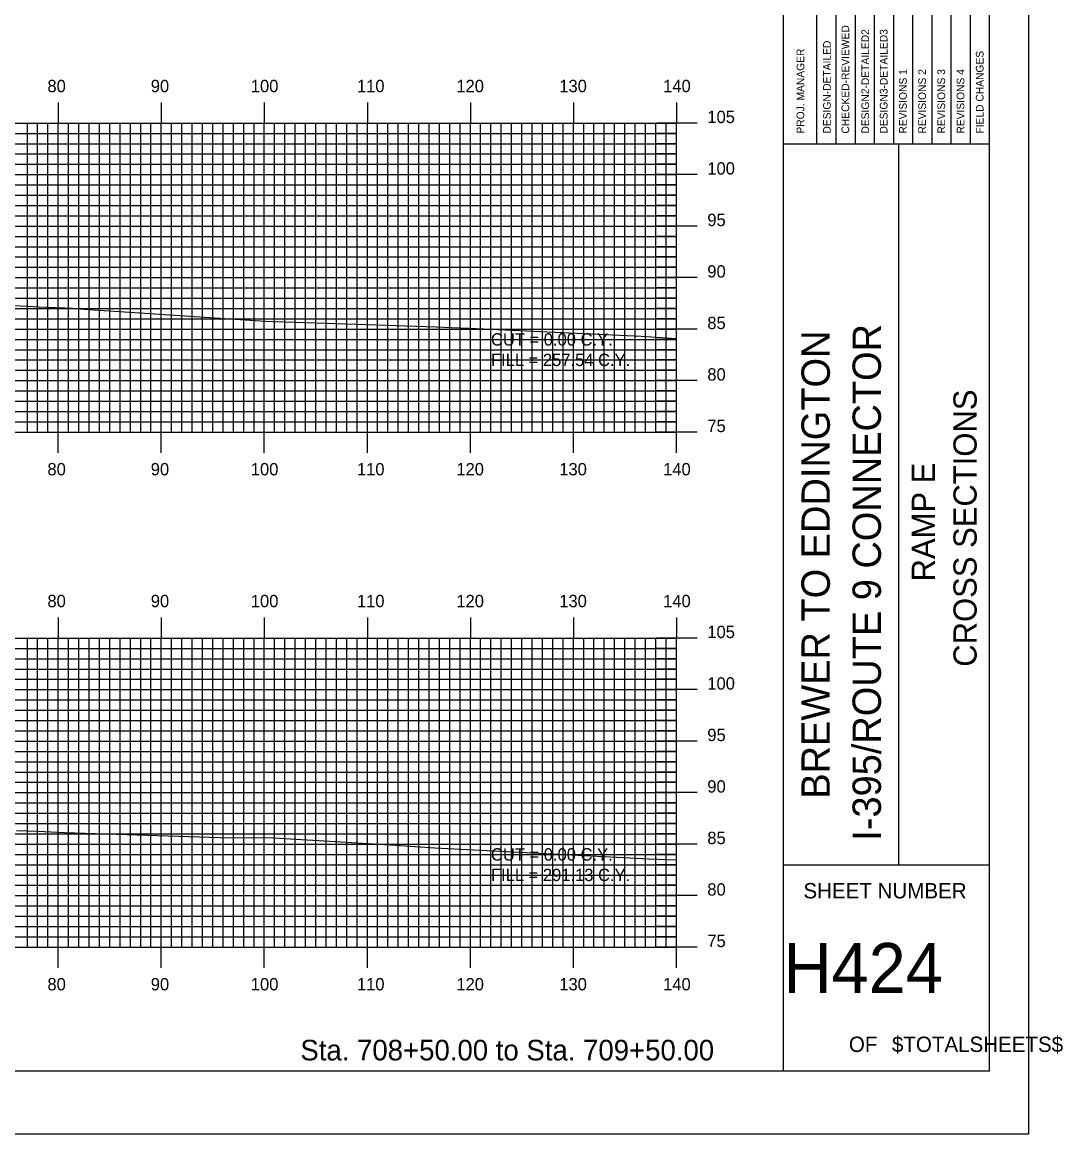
# Model space of a CAD drawing. Extents: x 854510 to 854853, y 364366 to 364586.
# Drawn here: x 854752.2 to 854853.2, y 364365.7 to 364473.6 of the extents above; entities that cross this region are included whole.
import ezdxf

# ---------------------------------------------------------------- set-up
doc = ezdxf.new("R2010")
doc.units = 0
for name, color, linetype in [('BORDER', 7, 'Continuous'), ('D_Text_Standard', 7, 'Continuous'), ('H_V ANNOTATION', 7, 'Continuous'), ('MAJOR', 7, 'Continuous'), ('MINOR', 7, 'Continuous'), ('PLOT BOUNDARY', 7, 'Continuous'), ('S_Roadway_Centerline', 7, 'Continuous')]:
    doc.layers.add(name, color=color, linetype=linetype)

msp = doc.modelspace()

# ---------------------------------------------------------------- linework, layer by layer
at = {"layer": 'BORDER'}
for p, q in [((854826.14, 364371.79), (854826.14, 364581.79)), ((854826.14, 364461.79), (854846.14, 364461.79)), ((854837.33, 364391.79), (854837.33, 364461.79)), ((854826.14, 364391.79), (854846.14, 364391.79))]:
    msp.add_line(p, q, dxfattribs=at)
msp.add_lwpolyline([(854526.14, 364371.79), (854846.14, 364371.79), (854846.14, 364581.79), (854526.14, 364581.79)], close=True, dxfattribs=at)
for points in [[(854831.24, 364461.8), (854831.24, 364496.79)], [(854833.1, 364496.79), (854833.1, 364461.8)], [(854834.97, 364461.8), (854834.97, 364496.79)], [(854836.83, 364461.8), (854836.83, 364496.79)], [(854838.69, 364461.8), (854838.69, 364496.79)], [(854840.56, 364461.8), (854840.56, 364496.79)], [(854842.42, 364461.8), (854842.42, 364496.79)], [(854844.28, 364461.8), (854844.28, 364496.79)], [(854829.38, 364461.8), (854829.38, 364495.38)]]:
    msp.add_lwpolyline(points, dxfattribs=at)
at = {"layer": 'MAJOR'}
for p, q in [((854755.74, 364465.79), (854755.74, 364463.79)), ((854765.74, 364465.79), (854765.74, 364463.79)), ((854775.74, 364465.79), (854775.74, 364463.79)), ((854785.74, 364465.79), (854785.74, 364463.79)), ((854795.74, 364465.79), (854795.74, 364463.79)), ((854805.74, 364465.79), (854805.74, 364463.79)), ((854815.74, 364465.79), (854815.74, 364463.79)), ((854535.74, 364463.79), (854815.74, 364463.79)), ((854535.74, 364463.79), (854815.74, 364463.79)), ((854755.74, 364433.79), (854755.74, 364463.79)), ((854765.74, 364433.79), (854765.74, 364463.79)), ((854775.74, 364433.79), (854775.74, 364463.79)), ((854785.74, 364433.79), (854785.74, 364463.79)), ((854795.74, 364433.79), (854795.74, 364463.79)), ((854805.74, 364433.79), (854805.74, 364463.79)), ((854817.75, 364463.79), (854813.74, 364463.79)), ((854815.74, 364433.79), (854815.74, 364463.79)), ((854815.74, 364433.79), (854815.74, 364463.79)), ((854535.74, 364458.79), (854815.74, 364458.79)), ((854817.75, 364458.79), (854813.74, 364458.79)), ((854535.74, 364453.79), (854815.74, 364453.79)), ((854817.75, 364453.79), (854813.74, 364453.79)), ((854535.74, 364448.79), (854815.74, 364448.79)), ((854817.75, 364448.79), (854813.74, 364448.79)), ((854535.74, 364443.79), (854815.74, 364443.79)), ((854817.75, 364443.79), (854813.74, 364443.79)), ((854535.74, 364438.79), (854815.74, 364438.79)), ((854817.75, 364438.79), (854813.74, 364438.79)), ((854535.74, 364433.79), (854815.74, 364433.79)), ((854535.74, 364433.79), (854815.74, 364433.79)), ((854755.74, 364431.78), (854755.74, 364433.79)), ((854765.74, 364431.78), (854765.74, 364433.79)), ((854775.74, 364431.78), (854775.74, 364433.79)), ((854785.74, 364431.78), (854785.74, 364433.79)), ((854795.74, 364431.78), (854795.74, 364433.79)), ((854805.74, 364431.78), (854805.74, 364433.79)), ((854817.75, 364433.79), (854813.74, 364433.79)), ((854815.74, 364431.78), (854815.74, 364433.79)), ((854755.74, 364415.79), (854755.74, 364413.79)), ((854765.74, 364415.79), (854765.74, 364413.79)), ((854775.74, 364415.79), (854775.74, 364413.79)), ((854785.74, 364415.79), (854785.74, 364413.79)), ((854795.74, 364415.79), (854795.74, 364413.79)), ((854805.74, 364415.79), (854805.74, 364413.79)), ((854815.74, 364415.79), (854815.74, 364413.79)), ((854535.74, 364413.79), (854815.74, 364413.79)), ((854535.74, 364413.79), (854815.74, 364413.79)), ((854755.74, 364383.79), (854755.74, 364413.79)), ((854765.74, 364383.79), (854765.74, 364413.79)), ((854775.74, 364383.79), (854775.74, 364413.79)), ((854785.74, 364383.79), (854785.74, 364413.79)), ((854795.74, 364383.79), (854795.74, 364413.79)), ((854805.74, 364383.79), (854805.74, 364413.79)), ((854817.75, 364413.79), (854813.74, 364413.79)), ((854815.74, 364383.79), (854815.74, 364413.79)), ((854815.74, 364383.79), (854815.74, 364413.79)), ((854535.74, 364408.79), (854815.74, 364408.79)), ((854817.75, 364408.79), (854813.74, 364408.79)), ((854535.74, 364403.79), (854815.74, 364403.79)), ((854817.75, 364403.79), (854813.74, 364403.79)), ((854535.74, 364398.79), (854815.74, 364398.79)), ((854817.75, 364398.79), (854813.74, 364398.79)), ((854535.74, 364393.79), (854815.74, 364393.79)), ((854817.75, 364393.79), (854813.74, 364393.79)), ((854535.74, 364388.79), (854815.74, 364388.79)), ((854817.75, 364388.79), (854813.74, 364388.79)), ((854535.74, 364383.79), (854815.74, 364383.79)), ((854535.74, 364383.79), (854815.74, 364383.79)), ((854755.74, 364381.78), (854755.74, 364383.79)), ((854765.74, 364381.78), (854765.74, 364383.79)), ((854775.74, 364381.78), (854775.74, 364383.79)), ((854785.74, 364381.78), (854785.74, 364383.79)), ((854795.74, 364381.78), (854795.74, 364383.79)), ((854805.74, 364381.78), (854805.74, 364383.79)), ((854817.75, 364383.79), (854813.74, 364383.79)), ((854815.74, 364381.78), (854815.74, 364383.79))]:
    msp.add_line(p, q, dxfattribs=at)
at = {"layer": 'MINOR'}
for p, q in [((854752.74, 364433.79), (854752.74, 364463.79)), ((854753.74, 364433.79), (854753.74, 364463.79)), ((854754.74, 364433.79), (854754.74, 364463.79)), ((854756.74, 364433.79), (854756.74, 364463.79)), ((854757.74, 364433.79), (854757.74, 364463.79)), ((854758.74, 364433.79), (854758.74, 364463.79)), ((854759.74, 364433.79), (854759.74, 364463.79)), ((854760.74, 364433.79), (854760.74, 364463.79)), ((854761.74, 364433.79), (854761.74, 364463.79)), ((854762.74, 364433.79), (854762.74, 364463.79)), ((854763.74, 364433.79), (854763.74, 364463.79)), ((854764.74, 364433.79), (854764.74, 364463.79)), ((854766.74, 364433.79), (854766.74, 364463.79)), ((854767.74, 364433.79), (854767.74, 364463.79)), ((854768.74, 364433.79), (854768.74, 364463.79)), ((854769.74, 364433.79), (854769.74, 364463.79)), ((854770.74, 364433.79), (854770.74, 364463.79)), ((854771.74, 364433.79), (854771.74, 364463.79)), ((854772.74, 364433.79), (854772.74, 364463.79)), ((854773.74, 364433.79), (854773.74, 364463.79)), ((854774.74, 364433.79), (854774.74, 364463.79)), ((854776.74, 364433.79), (854776.74, 364463.79)), ((854777.74, 364433.79), (854777.74, 364463.79)), ((854778.74, 364433.79), (854778.74, 364463.79)), ((854779.74, 364433.79), (854779.74, 364463.79)), ((854780.74, 364433.79), (854780.74, 364463.79)), ((854781.74, 364433.79), (854781.74, 364463.79)), ((854782.74, 364433.79), (854782.74, 364463.79)), ((854783.74, 364433.79), (854783.74, 364463.79)), ((854784.74, 364433.79), (854784.74, 364463.79)), ((854786.74, 364433.79), (854786.74, 364463.79)), ((854787.74, 364433.79), (854787.74, 364463.79)), ((854788.74, 364433.79), (854788.74, 364463.79)), ((854789.74, 364433.79), (854789.74, 364463.79)), ((854790.74, 364433.79), (854790.74, 364463.79)), ((854791.74, 364433.79), (854791.74, 364463.79)), ((854792.74, 364433.79), (854792.74, 364463.79)), ((854793.74, 364433.79), (854793.74, 364463.79)), ((854794.74, 364433.79), (854794.74, 364463.79)), ((854796.74, 364433.79), (854796.74, 364463.79)), ((854797.74, 364433.79), (854797.74, 364463.79)), ((854798.74, 364433.79), (854798.74, 364463.79)), ((854799.74, 364433.79), (854799.74, 364463.79)), ((854800.74, 364433.79), (854800.74, 364463.79)), ((854801.74, 364433.79), (854801.74, 364463.79)), ((854802.74, 364433.79), (854802.74, 364463.79)), ((854803.74, 364433.79), (854803.74, 364463.79)), ((854804.74, 364433.79), (854804.74, 364463.79)), ((854806.74, 364433.79), (854806.74, 364463.79)), ((854807.74, 364433.79), (854807.74, 364463.79)), ((854808.74, 364433.79), (854808.74, 364463.79)), ((854809.74, 364433.79), (854809.74, 364463.79)), ((854810.74, 364433.79), (854810.74, 364463.79)), ((854811.74, 364433.79), (854811.74, 364463.79)), ((854812.74, 364433.79), (854812.74, 364463.79)), ((854813.74, 364433.79), (854813.74, 364463.79)), ((854814.74, 364433.79), (854814.74, 364463.79)), ((854535.74, 364462.79), (854815.74, 364462.79)), ((854815.74, 364462.79), (854813.74, 364462.79)), ((854535.74, 364461.79), (854815.74, 364461.79)), ((854815.74, 364461.79), (854813.74, 364461.79)), ((854535.74, 364460.79), (854815.74, 364460.79)), ((854815.74, 364460.79), (854813.74, 364460.79)), ((854535.74, 364459.79), (854815.74, 364459.79)), ((854815.74, 364459.79), (854813.74, 364459.79)), ((854535.74, 364457.79), (854815.74, 364457.79)), ((854535.74, 364456.79), (854815.74, 364456.79)), ((854815.74, 364457.79), (854813.74, 364457.79)), ((854815.74, 364456.79), (854813.74, 364456.79)), ((854535.74, 364455.79), (854815.74, 364455.79)), ((854815.74, 364455.79), (854813.74, 364455.79)), ((854535.74, 364454.79), (854815.74, 364454.79)), ((854815.74, 364454.79), (854813.74, 364454.79)), ((854535.74, 364452.79), (854815.74, 364452.79)), ((854815.74, 364452.79), (854813.74, 364452.79)), ((854535.74, 364451.79), (854815.74, 364451.79)), ((854815.74, 364451.79), (854813.74, 364451.79)), ((854535.74, 364450.79), (854815.74, 364450.79)), ((854815.74, 364450.79), (854813.74, 364450.79)), ((854535.74, 364449.79), (854815.74, 364449.79)), ((854815.74, 364449.79), (854813.74, 364449.79)), ((854535.74, 364447.79), (854815.74, 364447.79)), ((854815.74, 364447.79), (854813.74, 364447.79)), ((854535.74, 364446.79), (854815.74, 364446.79)), ((854815.74, 364446.79), (854813.74, 364446.79)), ((854535.74, 364445.79), (854815.74, 364445.79)), ((854815.74, 364445.79), (854813.74, 364445.79)), ((854535.74, 364444.79), (854815.74, 364444.79)), ((854815.74, 364444.79), (854813.74, 364444.79)), ((854535.74, 364442.79), (854815.74, 364442.79)), ((854815.74, 364442.79), (854813.74, 364442.79)), ((854535.74, 364441.79), (854815.74, 364441.79)), ((854815.74, 364441.79), (854813.74, 364441.79)), ((854535.74, 364440.79), (854815.74, 364440.79)), ((854815.74, 364440.79), (854813.74, 364440.79)), ((854535.74, 364439.79), (854815.74, 364439.79)), ((854815.74, 364439.79), (854813.74, 364439.79)), ((854535.74, 364437.79), (854815.74, 364437.79)), ((854815.74, 364437.79), (854813.74, 364437.79)), ((854535.74, 364436.79), (854815.74, 364436.79)), ((854815.74, 364436.79), (854813.74, 364436.79)), ((854535.74, 364435.79), (854815.74, 364435.79)), ((854815.74, 364435.79), (854813.74, 364435.79)), ((854535.74, 364434.79), (854815.74, 364434.79)), ((854815.74, 364434.79), (854813.74, 364434.79)), ((854752.74, 364383.79), (854752.74, 364413.79)), ((854753.74, 364383.79), (854753.74, 364413.79)), ((854754.74, 364383.79), (854754.74, 364413.79)), ((854756.74, 364383.79), (854756.74, 364413.79)), ((854757.74, 364383.79), (854757.74, 364413.79)), ((854758.74, 364383.79), (854758.74, 364413.79)), ((854759.74, 364383.79), (854759.74, 364413.79)), ((854760.74, 364383.79), (854760.74, 364413.79)), ((854761.74, 364383.79), (854761.74, 364413.79)), ((854762.74, 364383.79), (854762.74, 364413.79)), ((854763.74, 364383.79), (854763.74, 364413.79)), ((854764.74, 364383.79), (854764.74, 364413.79)), ((854766.74, 364383.79), (854766.74, 364413.79)), ((854767.74, 364383.79), (854767.74, 364413.79)), ((854768.74, 364383.79), (854768.74, 364413.79)), ((854769.74, 364383.79), (854769.74, 364413.79)), ((854770.74, 364383.79), (854770.74, 364413.79)), ((854771.74, 364383.79), (854771.74, 364413.79)), ((854772.74, 364383.79), (854772.74, 364413.79)), ((854773.74, 364383.79), (854773.74, 364413.79)), ((854774.74, 364383.79), (854774.74, 364413.79)), ((854776.74, 364383.79), (854776.74, 364413.79)), ((854777.74, 364383.79), (854777.74, 364413.79)), ((854778.74, 364383.79), (854778.74, 364413.79)), ((854779.74, 364383.79), (854779.74, 364413.79)), ((854780.74, 364383.79), (854780.74, 364413.79)), ((854781.74, 364383.79), (854781.74, 364413.79)), ((854782.74, 364383.79), (854782.74, 364413.79)), ((854783.74, 364383.79), (854783.74, 364413.79)), ((854784.74, 364383.79), (854784.74, 364413.79)), ((854786.74, 364383.79), (854786.74, 364413.79)), ((854787.74, 364383.79), (854787.74, 364413.79)), ((854788.74, 364383.79), (854788.74, 364413.79)), ((854789.74, 364383.79), (854789.74, 364413.79)), ((854790.74, 364383.79), (854790.74, 364413.79)), ((854791.74, 364383.79), (854791.74, 364413.79)), ((854792.74, 364383.79), (854792.74, 364413.79)), ((854793.74, 364383.79), (854793.74, 364413.79)), ((854794.74, 364383.79), (854794.74, 364413.79)), ((854796.74, 364383.79), (854796.74, 364413.79)), ((854797.74, 364383.79), (854797.74, 364413.79)), ((854798.74, 364383.79), (854798.74, 364413.79)), ((854799.74, 364383.79), (854799.74, 364413.79)), ((854800.74, 364383.79), (854800.74, 364413.79)), ((854801.74, 364383.79), (854801.74, 364413.79)), ((854802.74, 364383.79), (854802.74, 364413.79)), ((854803.74, 364383.79), (854803.74, 364413.79)), ((854804.74, 364383.79), (854804.74, 364413.79)), ((854806.74, 364383.79), (854806.74, 364413.79)), ((854807.74, 364383.79), (854807.74, 364413.79)), ((854808.74, 364383.79), (854808.74, 364413.79)), ((854809.74, 364383.79), (854809.74, 364413.79)), ((854810.74, 364383.79), (854810.74, 364413.79)), ((854811.74, 364383.79), (854811.74, 364413.79)), ((854812.74, 364383.79), (854812.74, 364413.79)), ((854813.74, 364383.79), (854813.74, 364413.79)), ((854814.74, 364383.79), (854814.74, 364413.79)), ((854535.74, 364412.79), (854815.74, 364412.79)), ((854815.74, 364412.79), (854813.74, 364412.79)), ((854535.74, 364411.79), (854815.74, 364411.79)), ((854815.74, 364411.79), (854813.74, 364411.79)), ((854535.74, 364410.79), (854815.74, 364410.79)), ((854815.74, 364410.79), (854813.74, 364410.79)), ((854535.74, 364409.79), (854815.74, 364409.79)), ((854815.74, 364409.79), (854813.74, 364409.79)), ((854535.74, 364407.79), (854815.74, 364407.79)), ((854815.74, 364407.79), (854813.74, 364407.79)), ((854535.74, 364406.79), (854815.74, 364406.79)), ((854815.74, 364406.79), (854813.74, 364406.79)), ((854535.74, 364405.79), (854815.74, 364405.79)), ((854815.74, 364405.79), (854813.74, 364405.79)), ((854535.74, 364404.79), (854815.74, 364404.79)), ((854815.74, 364404.79), (854813.74, 364404.79)), ((854535.74, 364402.79), (854815.74, 364402.79)), ((854815.74, 364402.79), (854813.74, 364402.79)), ((854535.74, 364401.79), (854815.74, 364401.79)), ((854815.74, 364401.79), (854813.74, 364401.79)), ((854535.74, 364400.79), (854815.74, 364400.79)), ((854815.74, 364400.79), (854813.74, 364400.79)), ((854535.74, 364399.79), (854815.74, 364399.79)), ((854815.74, 364399.79), (854813.74, 364399.79)), ((854535.74, 364397.79), (854815.74, 364397.79)), ((854815.74, 364397.79), (854813.74, 364397.79)), ((854535.74, 364396.79), (854815.74, 364396.79)), ((854815.74, 364396.79), (854813.74, 364396.79)), ((854535.74, 364395.79), (854815.74, 364395.79)), ((854815.74, 364395.79), (854813.74, 364395.79)), ((854535.74, 364394.79), (854815.74, 364394.79)), ((854815.74, 364394.79), (854813.74, 364394.79)), ((854535.74, 364392.79), (854815.74, 364392.79)), ((854815.74, 364392.79), (854813.74, 364392.79)), ((854535.74, 364391.79), (854815.74, 364391.79)), ((854815.74, 364391.79), (854813.74, 364391.79)), ((854535.74, 364390.79), (854815.74, 364390.79)), ((854815.74, 364390.79), (854813.74, 364390.79)), ((854535.74, 364389.79), (854815.74, 364389.79)), ((854815.74, 364389.79), (854813.74, 364389.79)), ((854535.74, 364387.79), (854815.74, 364387.79)), ((854815.74, 364387.79), (854813.74, 364387.79)), ((854535.74, 364386.79), (854815.74, 364386.79)), ((854815.74, 364386.79), (854813.74, 364386.79)), ((854535.74, 364385.79), (854815.74, 364385.79)), ((854815.74, 364385.79), (854813.74, 364385.79)), ((854535.74, 364384.79), (854815.74, 364384.79)), ((854815.74, 364384.79), (854813.74, 364384.79))]:
    msp.add_line(p, q, dxfattribs=at)
at = {"layer": 'PLOT BOUNDARY'}
msp.add_lwpolyline([(854509.96, 364365.67), (854849.96, 364365.67), (854849.96, 364585.67), (854509.96, 364585.67)], close=True, dxfattribs=at)
at = {"layer": 'S_Roadway_Centerline'}
for points in [[(854643.39, 364448.07), (854657.11, 364448), (854660.48, 364447.92), (854662.11, 364448), (854672.41, 364448.25), (854680.7, 364447.97), (854691.25, 364447.79), (854699.92, 364447.6), (854711.56, 364447.4), (854718.4, 364447.33), (854720.58, 364447.16), (854724.13, 364447.09), (854738.1, 364446.75), (854754.56, 364445.93), (854756.42, 364445.84), (854757.11, 364445.82), (854758.25, 364445.73), (854775.82, 364444.56), (854792.41, 364444.01), (854793.87, 364443.95), (854795.63, 364443.87), (854812.32, 364443.11), (854815.74, 364442.88)], [(854751.7, 364395.12), (854753.72, 364395.06), (854756.34, 364394.93), (854771.45, 364394.42), (854776.67, 364394.41), (854783.68, 364393.98), (854788.47, 364393.69), (854792.29, 364393.44), (854811.21, 364392.45), (854813.02, 364392.37), (854815.74, 364392.26)]]:
    msp.add_lwpolyline(points, dxfattribs=at)

# ---------------------------------------------------------------- texts
at = {"layer": 'BORDER'}
for s, height, p in [('CHECKED-REVIEWED', 0.7455, (854832.51, 364462.77)), ('DESIGN2-DETAILED2', 0.7455, (854834.44, 364462.77)), ('DESIGN3-DETAILED3', 0.7455, (854836.23, 364462.77)), ('PROJ. MANAGER', 0.7455, (854828.15, 364462.77)), ('DESIGN-DETAILED', 0.7455, (854830.72, 364462.77)), ('FIELD CHANGES', 0.7455, (854845.55, 364462.77)), ('REVISIONS 1', 0.7455, (854838.1, 364462.77)), ('REVISIONS 2', 0.7455, (854839.96, 364462.77)), ('REVISIONS 3', 0.7455, (854841.82, 364462.77)), ('REVISIONS 4', 0.7455, (854843.69, 364462.77)), ('I-395/ROUTE 9 CONNECTOR', 2.7557, (854835.59, 364394.12)), ('BREWER TO EDDINGTON', 2.7557, (854830.63, 364398.2)), ('CROSS SECTIONS', 2.25, (854844.88, 364411.01)), ('RAMP E', 2.25, (854840.83, 364419.29))]:
    msp.add_text(s, height=height, rotation=90, dxfattribs=at).set_placement(p)
for s, height, p in [('SHEET NUMBER', 1.4905, (854828.07, 364388.52)), ('H424', 4.839, (854826.13, 364379.35)), ('OF', 1.491, (854832.48, 364373.61)), ('$TOTALSHEETS$', 1.4905, (854836.66, 364373.61))]:
    msp.add_text(s, height=height, dxfattribs=at).set_placement(p)
at = {"layer": 'D_Text_Standard'}
for s, p in [('CUT = 0.00 C.Y.', (854797.74, 364442.19)), ('FILL = 257.54 C.Y.', (854797.74, 364440.2)), ('CUT = 0.00 C.Y.', (854797.74, 364392.19)), ('FILL = 291.13 C.Y.', (854797.74, 364390.2))]:
    msp.add_text(s, height=1.2, dxfattribs=at).set_placement(p)
at = {"layer": 'H_V ANNOTATION'}
for s, height, p in [('80', 1.2, (854754.69, 364466.79)), ('90', 1.2, (854764.72, 364466.79)), ('100', 1.2, (854774.43, 364466.79)), ('110', 1.2, (854784.73, 364466.79)), ('120', 1.2, (854794.38, 364466.79)), ('130', 1.2, (854804.37, 364466.79)), ('140', 1.2, (854814.45, 364466.79)), ('105', 1.2, (854818.74, 364463.79)), ('100', 1.2, (854818.74, 364458.79)), ('95', 1.2, (854818.74, 364453.79)), ('90', 1.2, (854818.74, 364448.79)), ('85', 1.2, (854818.74, 364443.79)), ('80', 1.2, (854818.74, 364438.79)), ('75', 1.2, (854818.74, 364433.79)), ('80', 1.2, (854754.69, 364429.59)), ('90', 1.2, (854764.72, 364429.59)), ('100', 1.2, (854774.43, 364429.59)), ('110', 1.2, (854784.73, 364429.59)), ('120', 1.2, (854794.38, 364429.59)), ('130', 1.2, (854804.37, 364429.59)), ('140', 1.2, (854814.45, 364429.59)), ('80', 1.2, (854754.69, 364416.79)), ('90', 1.2, (854764.72, 364416.79)), ('100', 1.2, (854774.43, 364416.79)), ('110', 1.2, (854784.73, 364416.79)), ('120', 1.2, (854794.38, 364416.79)), ('130', 1.2, (854804.37, 364416.79)), ('140', 1.2, (854814.45, 364416.79)), ('105', 1.2, (854818.74, 364413.79)), ('100', 1.2, (854818.74, 364408.79)), ('95', 1.2, (854818.74, 364403.79)), ('90', 1.2, (854818.74, 364398.79)), ('85', 1.2, (854818.74, 364393.79)), ('80', 1.2, (854818.74, 364388.79)), ('75', 1.2, (854818.74, 364383.79)), ('80', 1.2, (854754.69, 364379.59)), ('90', 1.2, (854764.72, 364379.59)), ('100', 1.2, (854774.43, 364379.59)), ('110', 1.2, (854784.73, 364379.59)), ('120', 1.2, (854794.38, 364379.59)), ('130', 1.2, (854804.37, 364379.59)), ('140', 1.2, (854814.45, 364379.59)), ('Sta. 708+50.00 to Sta. 709+50.00', 2.0004, (854779.24, 364372.79))]:
    msp.add_text(s, height=height, dxfattribs=at).set_placement(p)

doc.saveas('drawing.dxf')
